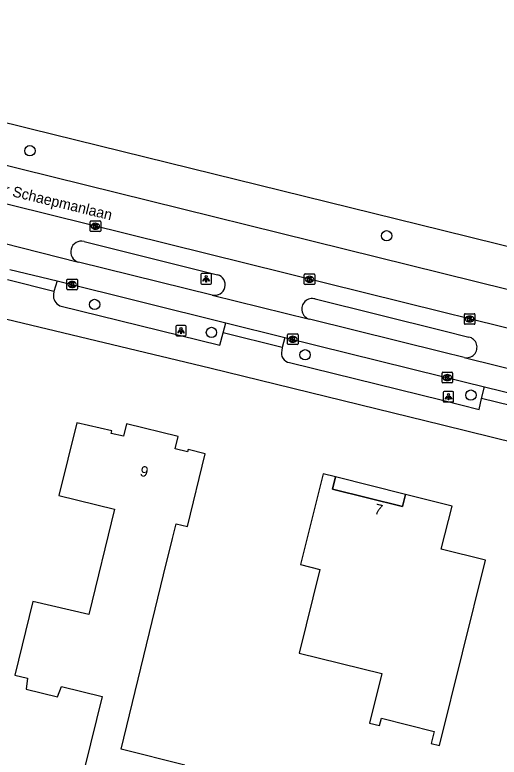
# Model space of a CAD drawing. Extents: x 161141 to 161601, y 381708 to 382245.
# Drawn here: x 161459.5 to 161505.4, y 382126.6 to 382197 of the extents above; entities that cross this region are included whole.
import ezdxf

# ---------------------------------------------------------------- set-up
doc = ezdxf.new("R2010")
doc.units = 0
for name, color, linetype in [('IMGEO_Boom', 7, 'Continuous'), ('IMGEO_Fietspad_gesloten', 7, 'Continuous'), ('IMGEO_Kolk', 7, 'Continuous'), ('IMGEO_Lichtpunt', 7, 'Continuous'), ('IMGEO_Openbare_ruimte_label', 7, 'Continuous'), ('IMGEO_Pand', 7, 'Continuous'), ('IMGEO_Pand_nummerreeks', 7, 'Continuous'), ('IMGEO_Pand_overbouw', 7, 'Continuous'), ('IMGEO_Parkeervlak_open', 7, 'Continuous'), ('IMGEO_Rijbaan_lokaal_gesloten', 7, 'Continuous'), ('IMGEO_Voetpad_open', 7, 'Continuous')]:
    doc.layers.add(name, color=color, linetype=linetype)

msp = doc.modelspace()

# ---------------------------------------------------------------- linework, layer by layer
at = {"layer": 'IMGEO_Boom'}
for centre in [(161460.901, 382184.081), (161494.721, 382176.011), (161467.035, 382169.5), (161478.112, 382166.848), (161486.986, 382164.728), (161502.714, 382160.905)]:
    msp.add_circle(centre, 0.489, dxfattribs=at)
at = {"layer": 'IMGEO_Fietspad_gesloten'}
for points in [[(161458.283, 382175.333), (161465.508, 382173.515)], [(161478.19, 382170.397), (161465.508, 382173.515)], [(161459.001, 382172.814), (161463.49, 382171.731)], [(161463.49, 382171.731), (161479.47, 382167.765)], [(161478.19, 382170.397), (161487.403, 382168.106)], [(161502.062, 382164.475), (161500, 382164.986), (161487.403, 382168.106)], [(161479.47, 382167.765), (161485.068, 382166.376)], [(161485.068, 382166.376), (161500, 382162.686), (161504.007, 382161.696)], [(161502.062, 382164.475), (161514.959, 382161.288)], [(161504.007, 382161.696), (161512.622, 382159.561)]]:
    msp.add_lwpolyline(points, dxfattribs=at)
at = {"layer": 'IMGEO_Kolk'}
for p, q in [((161466.605, 382176.495), (161466.605, 382177.347)), ((161466.68, 382177.421), (161467.532, 382177.421)), ((161467.606, 382177.347), (161467.606, 382176.495)), ((161467.116, 382176.641), (161467.091, 382176.641)), ((161467.093, 382177.201), (161467.118, 382177.201)), ((161467.532, 382176.421), (161466.68, 382176.421)), ((161486.905, 382171.466), (161486.905, 382172.318)), ((161486.98, 382172.392), (161487.832, 382172.392)), ((161487.906, 382172.318), (161487.906, 382171.466)), ((161464.398, 382170.969), (161464.398, 382171.821)), ((161464.473, 382171.895), (161465.325, 382171.895)), ((161464.886, 382171.675), (161464.911, 382171.675)), ((161465.399, 382171.821), (161465.399, 382170.969)), ((161487.416, 382171.612), (161487.391, 382171.612)), ((161487.393, 382172.172), (161487.418, 382172.172)), ((161465.325, 382170.895), (161464.473, 382170.895)), ((161464.909, 382171.115), (161464.884, 382171.115)), ((161487.832, 382171.392), (161486.98, 382171.392)), ((161502.09, 382167.698), (161502.09, 382168.55)), ((161502.165, 382168.624), (161503.017, 382168.624)), ((161502.578, 382168.404), (161502.603, 382168.404)), ((161503.091, 382168.55), (161503.091, 382167.698)), ((161503.017, 382167.624), (161502.165, 382167.624)), ((161502.601, 382167.844), (161502.576, 382167.844)), ((161485.393, 382166.703), (161486.245, 382166.703)), ((161485.318, 382165.777), (161485.318, 382166.629)), ((161485.806, 382166.483), (161485.831, 382166.483)), ((161486.319, 382166.629), (161486.319, 382165.777)), ((161486.245, 382165.703), (161485.393, 382165.703)), ((161485.829, 382165.923), (161485.804, 382165.923)), ((161499.972, 382162.143), (161499.972, 382162.995)), ((161500.047, 382163.069), (161500.899, 382163.069)), ((161500.46, 382162.849), (161500.485, 382162.849)), ((161500.973, 382162.995), (161500.973, 382162.143)), ((161500.899, 382162.069), (161500.047, 382162.069)), ((161500.483, 382162.289), (161500.458, 382162.289))]:
    msp.add_line(p, q, dxfattribs=at)
for points in [[(161466.605, 382176.495), (161466.605, 382177.347)], [(161466.68, 382177.421), (161467.532, 382177.421)], [(161467.606, 382177.347), (161467.606, 382176.495)], [(161466.926, 382177.121), (161467.049, 382177.121), (161467.049, 382176.97), (161467.179, 382177.121), (161467.343, 382177.121), (161467.197, 382176.97), (161467.35, 382176.721), (161467.198, 382176.721), (161467.113, 382176.885), (161467.049, 382176.818), (161467.049, 382176.721), (161466.926, 382176.721), (161466.926, 382177.121)], [(161467.532, 382176.421), (161466.68, 382176.421)], [(161486.905, 382171.466), (161486.905, 382172.318)], [(161486.98, 382172.392), (161487.832, 382172.392)], [(161487.906, 382172.318), (161487.906, 382171.466)], [(161464.398, 382170.969), (161464.398, 382171.821)], [(161464.473, 382171.895), (161465.325, 382171.895)], [(161464.719, 382171.595), (161464.842, 382171.595), (161464.842, 382171.444), (161464.972, 382171.595), (161465.136, 382171.595), (161464.99, 382171.444), (161465.143, 382171.195), (161464.991, 382171.195), (161464.906, 382171.359), (161464.842, 382171.292), (161464.842, 382171.195), (161464.719, 382171.195), (161464.719, 382171.595)], [(161465.399, 382171.821), (161465.399, 382170.969)], [(161487.226, 382172.092), (161487.349, 382172.092), (161487.349, 382171.941), (161487.479, 382172.092), (161487.643, 382172.092), (161487.497, 382171.941), (161487.65, 382171.692), (161487.498, 382171.692), (161487.413, 382171.856), (161487.349, 382171.789), (161487.349, 382171.692), (161487.226, 382171.692), (161487.226, 382172.092)], [(161465.325, 382170.895), (161464.473, 382170.895)], [(161487.832, 382171.392), (161486.98, 382171.392)], [(161502.09, 382167.698), (161502.09, 382168.55)], [(161502.165, 382168.624), (161503.017, 382168.624)], [(161502.411, 382168.324), (161502.534, 382168.324), (161502.534, 382168.173), (161502.664, 382168.324), (161502.828, 382168.324), (161502.682, 382168.173), (161502.835, 382167.924), (161502.683, 382167.924), (161502.598, 382168.088), (161502.534, 382168.021), (161502.534, 382167.924), (161502.411, 382167.924), (161502.411, 382168.324)], [(161503.091, 382168.55), (161503.091, 382167.698)], [(161503.017, 382167.624), (161502.165, 382167.624)], [(161485.393, 382166.703), (161486.245, 382166.703)], [(161485.318, 382165.777), (161485.318, 382166.629)], [(161485.639, 382166.403), (161485.762, 382166.403), (161485.762, 382166.252), (161485.892, 382166.403), (161486.056, 382166.403), (161485.91, 382166.252), (161486.063, 382166.003), (161485.911, 382166.003), (161485.826, 382166.167), (161485.762, 382166.1), (161485.762, 382166.003), (161485.639, 382166.003), (161485.639, 382166.403)], [(161486.319, 382166.629), (161486.319, 382165.777)], [(161486.245, 382165.703), (161485.393, 382165.703)], [(161499.972, 382162.143), (161499.972, 382162.995)], [(161500.047, 382163.069), (161500.899, 382163.069)], [(161500.293, 382162.769), (161500.416, 382162.769), (161500.416, 382162.618), (161500.546, 382162.769), (161500.71, 382162.769), (161500.564, 382162.618), (161500.717, 382162.369), (161500.565, 382162.369), (161500.48, 382162.533), (161500.416, 382162.466), (161500.416, 382162.369), (161500.293, 382162.369), (161500.293, 382162.769)], [(161500.973, 382162.995), (161500.973, 382162.143)], [(161500.899, 382162.069), (161500.047, 382162.069)]]:
    msp.add_lwpolyline(points, dxfattribs=at)
for centre, start, end in [((161466.682, 382177.345), 91.55205, 178.44795), ((161466.682, 382177.345), 91.55205, 178.44795), ((161467.53, 382177.345), 1.55205, 88.44795), ((161467.53, 382177.345), 1.55205, 88.44795), ((161466.682, 382176.497), 181.55205, 268.44795), ((161466.682, 382176.497), 181.55205, 268.44795), ((161467.53, 382176.497), 271.55205, 358.44795), ((161467.53, 382176.497), 271.55205, 358.44795), ((161486.982, 382172.316), 91.55205, 178.44795), ((161486.982, 382172.316), 91.55205, 178.44795), ((161487.83, 382172.316), 1.55205, 88.44795), ((161487.83, 382172.316), 1.55205, 88.44795), ((161464.475, 382171.819), 91.55205, 178.44795), ((161464.475, 382171.819), 91.55205, 178.44795), ((161465.323, 382171.819), 1.55205, 88.44795), ((161465.323, 382171.819), 1.55205, 88.44795), ((161464.475, 382170.971), 181.55205, 268.44795), ((161464.475, 382170.971), 181.55205, 268.44795), ((161465.323, 382170.971), 271.55205, 358.44795), ((161465.323, 382170.971), 271.55205, 358.44795), ((161486.982, 382171.468), 181.55205, 268.44795), ((161486.982, 382171.468), 181.55205, 268.44795), ((161487.83, 382171.468), 271.55205, 358.44795), ((161487.83, 382171.468), 271.55205, 358.44795), ((161502.167, 382168.548), 91.55205, 178.44795), ((161502.167, 382168.548), 91.55205, 178.44795), ((161503.015, 382168.548), 1.55205, 88.44795), ((161503.015, 382168.548), 1.55205, 88.44795), ((161502.167, 382167.7), 181.55205, 268.44795), ((161502.167, 382167.7), 181.55205, 268.44795), ((161503.015, 382167.7), 271.55205, 358.44795), ((161503.015, 382167.7), 271.55205, 358.44795), ((161485.395, 382166.627), 91.55205, 178.44795), ((161485.395, 382166.627), 91.55205, 178.44795), ((161486.243, 382166.627), 1.55205, 88.44795), ((161486.243, 382166.627), 1.55205, 88.44795), ((161485.395, 382165.779), 181.55205, 268.44795), ((161485.395, 382165.779), 181.55205, 268.44795), ((161486.243, 382165.779), 271.55205, 358.44795), ((161486.243, 382165.779), 271.55205, 358.44795), ((161500.049, 382162.993), 91.55205, 178.44795), ((161500.049, 382162.993), 91.55205, 178.44795), ((161500.897, 382162.993), 1.55205, 88.44795), ((161500.897, 382162.993), 1.55205, 88.44795), ((161500.049, 382162.145), 181.55205, 268.44795), ((161500.049, 382162.145), 181.55205, 268.44795), ((161500.897, 382162.145), 271.55205, 358.44795), ((161500.897, 382162.145), 271.55205, 358.44795)]:
    msp.add_arc(centre, 0.0765, start, end, dxfattribs=at)
for centre, major_axis, ratio, start_param, end_param in [((161467.092, 382176.921), (-0.387, 0.002), 0.722429, 4.712389, 7.853982), ((161467.117, 382176.921), (-0.39, 0.002), 0.717154, 1.570796, 4.712389), ((161464.885, 382171.395), (-0.387, 0.002), 0.722429, 4.712389, 7.853982), ((161464.91, 382171.395), (-0.39, 0.002), 0.717154, 1.570796, 4.712389), ((161487.392, 382171.892), (-0.387, 0.002), 0.722429, 4.712389, 7.853982), ((161487.417, 382171.892), (-0.39, 0.002), 0.717154, 1.570796, 4.712389), ((161502.577, 382168.124), (-0.387, 0.002), 0.722429, 4.712389, 7.853982), ((161502.602, 382168.124), (-0.39, 0.002), 0.717154, 1.570796, 4.712389), ((161485.805, 382166.203), (-0.387, 0.002), 0.722429, 4.712389, 7.853982), ((161485.83, 382166.203), (-0.39, 0.002), 0.717154, 1.570796, 4.712389), ((161500.459, 382162.569), (-0.387, 0.002), 0.722429, 4.712389, 7.853982), ((161500.484, 382162.569), (-0.39, 0.002), 0.717154, 1.570796, 4.712389)]:
    msp.add_ellipse(centre, major_axis=major_axis, ratio=ratio, start_param=start_param, end_param=end_param, dxfattribs=at)
at = {"layer": 'IMGEO_Lichtpunt'}
for p, q in [((161477.111, 382172.336), (161477.111, 382171.529)), ((161477.111, 382172.336), (161477.111, 382171.529)), ((161478.013, 382172.431), (161477.205, 382172.431)), ((161478.013, 382172.431), (161477.205, 382172.431)), ((161478.107, 382171.529), (161478.107, 382172.336)), ((161478.107, 382171.529), (161478.107, 382172.336)), ((161477.205, 382171.435), (161478.013, 382171.435)), ((161477.205, 382171.435), (161478.013, 382171.435)), ((161474.722, 382167.422), (161474.722, 382166.615)), ((161474.722, 382167.422), (161474.722, 382166.615)), ((161475.624, 382167.517), (161474.816, 382167.517)), ((161475.624, 382167.517), (161474.816, 382167.517)), ((161475.718, 382166.615), (161475.718, 382167.422)), ((161475.718, 382166.615), (161475.718, 382167.422)), ((161474.816, 382166.521), (161475.624, 382166.521)), ((161474.816, 382166.521), (161475.624, 382166.521)), ((161500.077, 382161.157), (161500.077, 382160.35)), ((161500.077, 382161.157), (161500.077, 382160.35)), ((161500.979, 382161.252), (161500.171, 382161.252)), ((161500.979, 382161.252), (161500.171, 382161.252)), ((161501.073, 382160.35), (161501.073, 382161.157)), ((161501.073, 382160.35), (161501.073, 382161.157)), ((161500.171, 382160.256), (161500.979, 382160.256)), ((161500.171, 382160.256), (161500.979, 382160.256))]:
    msp.add_line(p, q, dxfattribs=at)
for points in [[(161477.485, 382172), (161477.524, 382171.972), (161477.336, 382171.71), (161477.298, 382171.737), (161477.485, 382172)], [(161477.587, 382171.952), (161477.634, 382171.952), (161477.634, 382171.63), (161477.587, 382171.63), (161477.587, 382171.952)], [(161477.697, 382171.972), (161477.735, 382171.999), (161477.922, 382171.737), (161477.883, 382171.709), (161477.697, 382171.972)], [(161475.096, 382167.086), (161475.135, 382167.058), (161474.947, 382166.796), (161474.909, 382166.823), (161475.096, 382167.086)], [(161475.198, 382167.038), (161475.245, 382167.038), (161475.245, 382166.716), (161475.198, 382166.716), (161475.198, 382167.038)], [(161475.308, 382167.058), (161475.346, 382167.085), (161475.533, 382166.823), (161475.494, 382166.795), (161475.308, 382167.058)], [(161500.451, 382160.821), (161500.49, 382160.793), (161500.302, 382160.531), (161500.264, 382160.558), (161500.451, 382160.821)], [(161500.553, 382160.773), (161500.6, 382160.773), (161500.6, 382160.451), (161500.553, 382160.451), (161500.553, 382160.773)], [(161500.663, 382160.793), (161500.701, 382160.82), (161500.888, 382160.558), (161500.849, 382160.53), (161500.663, 382160.793)]]:
    msp.add_lwpolyline(points, dxfattribs=at)
for centre in [(161477.61, 382172.134), (161475.221, 382167.22), (161500.576, 382160.955)]:
    msp.add_circle(centre, 0.0994, dxfattribs=at)
for centre, start, end in [((161477.205, 382172.336), 90, 180), ((161477.205, 382172.336), 90, 180), ((161478.013, 382172.336), 0, 90), ((161478.013, 382172.336), 0, 90), ((161477.205, 382171.529), 180, 270), ((161477.205, 382171.529), 180, 270), ((161478.013, 382171.529), 270, 0), ((161478.013, 382171.529), 270, 360), ((161474.816, 382167.422), 90, 180), ((161474.816, 382167.422), 90, 180), ((161475.624, 382167.422), 0, 90), ((161475.624, 382167.422), 0, 90), ((161474.816, 382166.615), 180, 270), ((161474.816, 382166.615), 180, 270), ((161475.624, 382166.615), 270, 0), ((161475.624, 382166.615), 270, 360), ((161500.171, 382161.157), 90, 180), ((161500.171, 382161.157), 90, 180), ((161500.979, 382161.157), 0, 90), ((161500.979, 382161.157), 0, 90), ((161500.171, 382160.35), 180, 270), ((161500.171, 382160.35), 180, 270), ((161500.979, 382160.35), 270, 0), ((161500.979, 382160.35), 270, 360)]:
    msp.add_arc(centre, 0.0946, start, end, dxfattribs=at)
at = {"layer": 'IMGEO_Pand'}
for points in [[(161474.406, 382147.295), (161474.75, 382148.705), (161475.828, 382148.441), (161477.505, 382155.333), (161475.889, 382155.744), (161475.834, 382155.531), (161474.663, 382155.802), (161474.951, 382156.972), (161470.062, 382158.175), (161469.778, 382157.019), (161468.609, 382157.277), (161468.656, 382157.507), (161465.343, 382158.285), (161463.637, 382151.397), (161468.93, 382150.099), (161466.492, 382140.097), (161461.186, 382141.344), (161459.473, 382134.346), (161460.658, 382134.056), (161460.537, 382133.016), (161463.511, 382132.295), (161463.889, 382133.273), (161467.743, 382132.322), (161464.986, 382121.154)], [(161504.087, 382145.265), (161499.897, 382146.301), (161500.917, 382150.389), (161496.516, 382151.486), (161496.23, 382150.338), (161489.575, 382151.995), (161489.861, 382153.143), (161488.704, 382153.431), (161486.566, 382144.832), (161488.398, 382144.376), (161486.428, 382136.449), (161494.252, 382134.504), (161493.086, 382129.811), (161494.056, 382129.569), (161494.228, 382130.258), (161499.224, 382129.017), (161498.939, 382127.871), (161499.715, 382127.678), (161504.087, 382145.265)], [(161475.595, 382125.827), (161469.54, 382127.323), (161473.571, 382143.873), (161474.406, 382147.295)]]:
    msp.add_lwpolyline(points, dxfattribs=at)
at = {"layer": 'IMGEO_Pand_overbouw'}
msp.add_lwpolyline([(161496.516, 382151.486), (161489.861, 382153.143), (161489.575, 382151.995), (161496.23, 382150.338)], close=True, dxfattribs=at)
at = {"layer": 'IMGEO_Parkeervlak_open'}
for points in [[(161466.034, 382175.47), (161478.67, 382172.325)], [(161487.941, 382170.021), (161500, 382167.036), (161502.512, 382166.414)]]:
    msp.add_lwpolyline(points, dxfattribs=at)
for centre, radius, start, end in [((161465.777, 382174.491), 1.012, 75.26456, 254.61738), ((161478.421, 382171.363), 0.993, 256.55375, 75.48567), ((161487.668, 382169.065), 0.995, 74.09074, 254.52491), ((161502.293, 382165.443), 0.995, 256.55144, 77.31693)]:
    msp.add_arc(centre, radius, start, end, dxfattribs=at)
at = {"layer": 'IMGEO_Rijbaan_lokaal_gesloten'}
for points in [[(161417.456, 382196.964), (161420.058, 382196.306), (161460.894, 382186.197), (161500, 382176.547), (161558.491, 382162.113), (161560.838, 382161.565), (161562.428, 382161.253), (161571.347, 382159.936), (161575.364, 382159.517)], [(161416.542, 382193.184), (161418.72, 382192.635), (161459.898, 382182.379), (161500, 382172.465), (161568.862, 382155.44)], [(161571.771, 382151.019), (161502.587, 382168.125), (161500, 382168.766), (161459.102, 382178.908), (161420.449, 382188.487), (161415.442, 382189.785), (161412.878, 382190.505)]]:
    msp.add_lwpolyline(points, dxfattribs=at)
at = {"layer": 'IMGEO_Voetpad_open'}
for points in [[(161387.058, 382185.651), (161389.844, 382185.251), (161418.52, 382178.097), (161457.897, 382168.303), (161477.956, 382163.494), (161500, 382158.072), (161544.61, 382147.101), (161553.295, 382144.911), (161577.621, 382138.939), (161579.137, 382138.37)], [(161463.163, 382170.733), (161458.766, 382171.826)], [(161463.49, 382171.731), (161463.163, 382170.733)], [(161463.163, 382170.733), (161463.131, 382170.447)], [(161463.743, 382169.384), (161478.917, 382165.631), (161479.208, 382166.815)], [(161479.208, 382166.815), (161479.47, 382167.765)], [(161484.817, 382165.422), (161479.208, 382166.815)], [(161485.068, 382166.376), (161484.817, 382165.422)], [(161484.817, 382165.422), (161484.784, 382165.147)], [(161485.52, 382163.986), (161500, 382160.412), (161503.478, 382159.553), (161503.727, 382160.581)], [(161503.727, 382160.581), (161504.007, 382161.696)], [(161512.36, 382158.471), (161503.727, 382160.581)]]:
    msp.add_lwpolyline(points, dxfattribs=at)
for centre, radius, start, end in [((161464.108, 382170.302), 0.988, 171.54801, 248.31256), ((161485.635, 382164.873), 0.894, 162.15505, 262.58913)]:
    msp.add_arc(centre, radius, start, end, dxfattribs=at)

# ---------------------------------------------------------------- texts
at = {"layer": 'IMGEO_Openbare_ruimte_label'}
msp.add_text('Dr Schaepmanlaan', height=1, rotation=346.35276, dxfattribs=at).set_placement((161457.435, 382180.183))
at = {"layer": 'IMGEO_Pand_nummerreeks'}
for s, rotation, p in [('9', 345.61374, (161471.252, 382153.275)), ('7', 346.00264, (161493.476, 382149.667))]:
    msp.add_text(s, height=1, rotation=rotation, dxfattribs=at).set_placement(p)

doc.saveas('drawing.dxf')
